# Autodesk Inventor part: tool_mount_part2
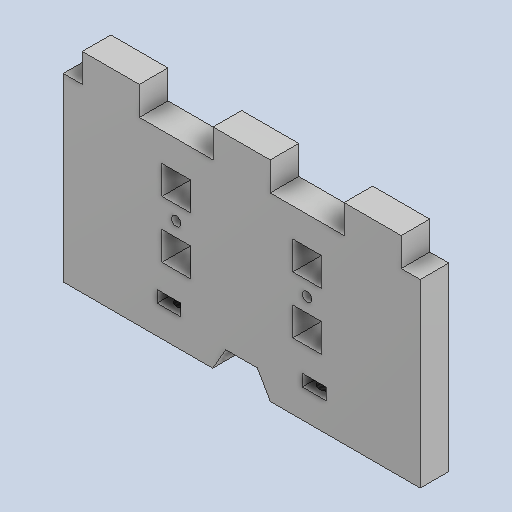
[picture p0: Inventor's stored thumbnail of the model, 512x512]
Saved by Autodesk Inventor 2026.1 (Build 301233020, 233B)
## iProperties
Created: 2026-10
Part Number: tool_mount_part2
Material: Steel
Document SubType Name: Modeling
Designer: hp
Density: 7.85 g/cm^3
Appearance: Default
Author: hp
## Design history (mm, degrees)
feature "Body1"
sketch "Sketch1"
  geometry: 1 further point
hole "Hole1" sketch "Sketch1" at (22.464, 3) diameter "d0" = 3.242; stored, may be unused: countersink angle "d4" = 90 deg, drill point angle "d6" = 120 deg; dims "d1" = 8, "d2" = 4, "d3" = 2, "d5" = 8.5
sketch "Sketch2"
  geometry: 1 further point
hole "Hole2" sketch "Sketch2" at (8.938, 3) diameter "d7" = 3.242; stored, may be unused: countersink angle "d11" = 90 deg, drill point angle "d13" = 120 deg; dims "d8" = 8, "d9" = 4, "d10" = 2, "d12" = 8.5
body "Solid1"
